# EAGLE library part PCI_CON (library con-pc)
PCI BOARD LONG
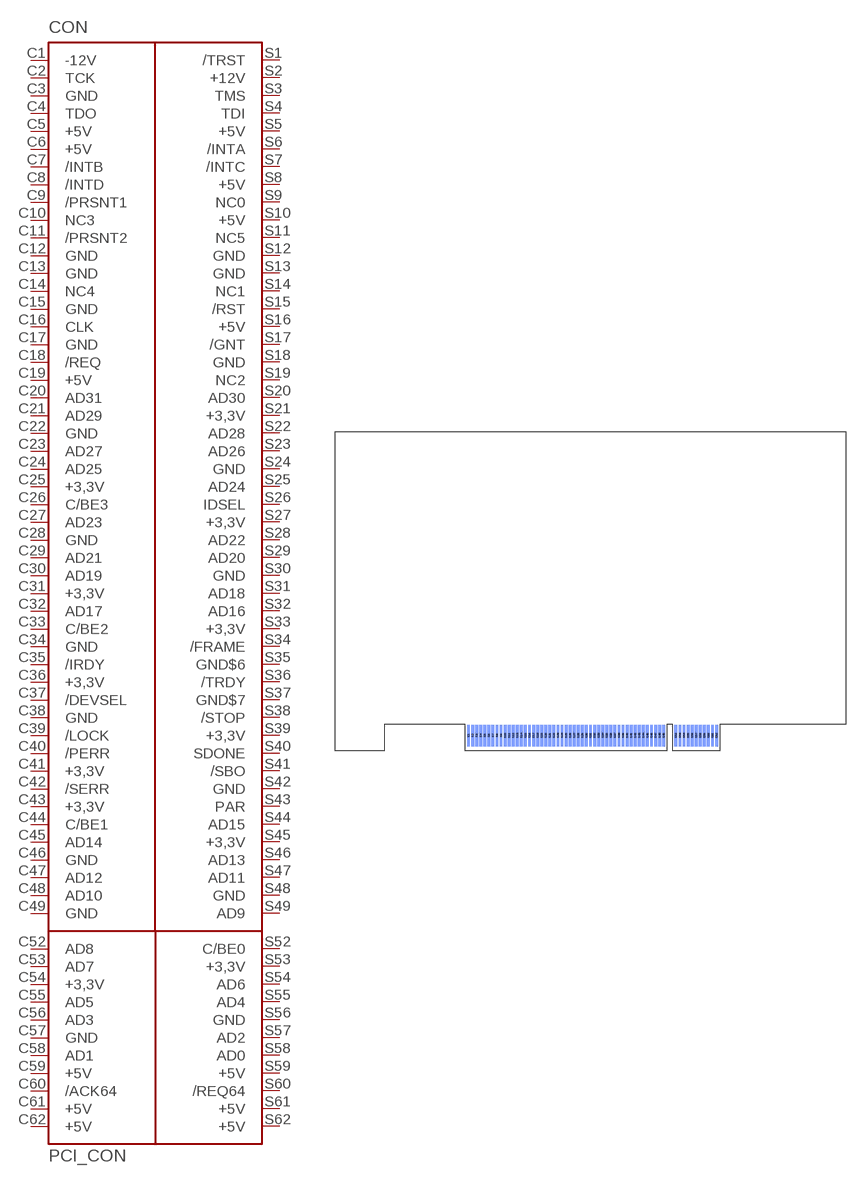
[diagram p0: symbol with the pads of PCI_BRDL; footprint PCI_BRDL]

Designator prefix CON

## PCI_CON  [PCI_BRDL]
C1  -12V  pwr
C2  TCK  pas
C3  GND  pwr
C4  TDO  pas
C5  +5V  pwr
C6  +5V  pwr
C7  /INTB  pas
C8  /INTD  pas
C9  /PRSNT1  pas
C10  NC3  pas
C11  /PRSNT2  pas
C12  GND  pas
C13  GND  pwr
C14  NC4  pas
C15  GND  pwr
C16  CLK  pas
C17  GND  pwr
C18  /REQ  pas
C19  +5V  pwr
C20  AD31  pas
C21  AD29  pas
C22  GND  pwr
C23  AD27  pas
C24  AD25  pas
C25  +3,3V  pwr
C26  C/BE3  pas
C27  AD23  pas
C28  GND  pwr
C29  AD21  pas
C30  AD19  pas
C31  +3,3V  pwr
C32  AD17  pas
C33  C/BE2  pas
C34  GND  pwr
C35  /IRDY  pas
C36  +3,3V  pwr
C37  /DEVSEL  pas
C38  GND  pwr
C39  /LOCK  pas
C40  /PERR  pas
C41  +3,3V  pwr
C42  /SERR  pas
C43  +3,3V  pwr
C44  C/BE1  pas
C45  AD14  pas
C46  GND  pwr
C47  AD12  pas
C48  AD10  pas
C49  GND  pwr
C52  AD8  pas
C53  AD7  pas
C54  +3,3V  pwr
C55  AD5  pas
C56  AD3  pas
C57  GND  pwr
C58  AD1  pas
C59  +5V  pwr
C60  /ACK64  pas
C61  +5V  pwr
C62  +5V  pwr
S1  /TRST  pas
S2  +12V  pwr
S3  TMS  pas
S4  TDI  pas
S5  +5V  pwr
S6  /INTA  pas
S7  /INTC  pas
S8  +5V  pwr
S9  NC0  pas
S10  +5V  pwr
S11  NC5  pas
S12  GND  pwr
S13  GND  pwr
S14  NC1  pas
S15  /RST  pas
S16  +5V  pwr
S17  /GNT  pas
S18  GND  pwr
S19  NC2  pas
S20  AD30  pas
S21  +3,3V  pwr
S22  AD28  pas
S23  AD26  pas
S24  GND  pwr
S25  AD24  pas
S26  IDSEL  pas
S27  +3,3V  pwr
S28  AD22  pas
S29  AD20  pas
S30  GND  pwr
S31  AD18  pas
S32  AD16  pas
S33  +3,3V  pwr
S34  /FRAME  pas
S35  GND$6  pwr
S36  /TRDY  pas
S37  GND$7  pas
S38  /STOP  pas
S39  +3,3V  pas
S40  SDONE  pas
S41  /SBO  pas
S42  GND  pwr
S43  PAR  pas
S44  AD15  pas
S45  +3,3V  pwr
S46  AD13  pas
S47  AD11  pas
S48  GND  pwr
S49  AD9  pas
S52  C/BE0  pas
S53  +3,3V  pwr
S54  AD6  pas
S55  AD4  pas
S56  GND  pwr
S57  AD2  pas
S58  AD0  pas
S59  +5V  pwr
S60  /REQ64  pas
S61  +5V  pwr
S62  +5V  pwr

## Footprint PCI_BRDL (pad centres in mm)
PCI BOARD LONG
smd 0.91 x 6.7: C1 41.593,4.763; C2 42.862,4.763; C3 44.133,4.763; C4 45.403,4.763; C5 46.672,4.763; C6 47.943,4.763; C7 49.212,4.763; C8 50.483,4.763; C9 51.752,4.763; C10 53.023,4.763; C11 54.292,4.763; C12 55.562,4.763; C13 56.833,4.763; C14 58.102,4.763; C15 59.373,4.763; C16 60.642,4.763; C17 61.913,4.763; C18 63.182,4.763; C19 64.453,4.763; C20 65.722,4.763; C21 66.993,4.763; C22 68.263,4.763; C23 69.532,4.763; C24 70.802,4.763; C25 72.073,4.763; C26 73.343,4.763; C27 74.612,4.763; C28 75.882,4.763; C29 77.153,4.763; C30 78.422,4.763; C31 79.692,4.763; C32 80.963,4.763; C33 82.233,4.763; C34 83.502,4.763; C35 84.772,4.763; C36 86.043,4.763; C37 87.312,4.763; C38 88.582,4.763; C39 89.853,4.763; C40 91.123,4.763; C41 92.392,4.763; C42 93.662,4.763; C43 94.933,4.763; C44 96.203,4.763; C45 97.472,4.763; C46 98.743,4.763; C47 100.013,4.763; C48 101.282,4.763; C49 102.552,4.763; C52 106.362,4.763; C53 107.632,4.763; C54 108.903,4.763; C55 110.172,4.763; C56 111.442,4.763; C57 112.713,4.763; C58 113.983,4.763; C59 115.252,4.763; C60 116.522,4.763; C61 117.793,4.763; C62 119.062,4.763
smd 0.91 x 6.7 bottom: S1 41.593,4.763; S2 42.862,4.763; S3 44.133,4.763; S4 45.403,4.763; S5 46.672,4.763; S6 47.943,4.763; S7 49.212,4.763; S8 50.483,4.763; S9 51.752,4.763; S10 53.023,4.763; S11 54.292,4.763; S12 55.562,4.763; S13 56.833,4.763; S14 58.102,4.763; S15 59.373,4.763; S16 60.642,4.763; S17 61.913,4.763; S18 63.182,4.763; S19 64.453,4.763; S20 65.722,4.763; S21 66.993,4.763; S22 68.263,4.763; S23 69.532,4.763; S24 70.802,4.763; S25 72.073,4.763; S26 73.343,4.763; S27 74.612,4.763; S28 75.882,4.763; S29 77.153,4.763; S30 78.422,4.763; S31 79.692,4.763; S32 80.963,4.763; S33 82.233,4.763; S34 83.502,4.763; S35 84.772,4.763; S36 86.043,4.763; S37 87.312,4.763; S38 88.582,4.763; S39 89.853,4.763; S40 91.123,4.763; S41 92.392,4.763; S42 93.662,4.763; S43 94.933,4.763; S44 96.203,4.763; S45 97.472,4.763; S46 98.743,4.763; S47 100.013,4.763; S48 101.282,4.763; S49 102.552,4.763; S52 106.362,4.763; S53 107.632,4.763; S54 108.903,4.763; S55 110.172,4.763; S56 111.442,4.763; S57 112.713,4.763; S58 113.983,4.763; S59 115.252,4.763; S60 116.522,4.763; S61 117.793,4.763; S62 119.062,4.763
